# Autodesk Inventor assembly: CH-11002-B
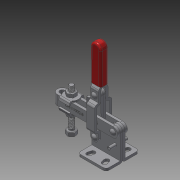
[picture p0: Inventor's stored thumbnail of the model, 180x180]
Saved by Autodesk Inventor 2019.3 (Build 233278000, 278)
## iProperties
Company: Î¢ÈíÖÐ¹ú
Created: 2012-09
Part Number: CH-11002-B
Material: Ogólny
Description: STEP AP203
Document SubType Name: Assembly
Designer: CADENGINEERING4
Stock Number: DOCISK PIONOWY
Sending System: SolidWorks 2010
Preprocessor: SwSTEP 2.0
Title: CH-11002-B.STEP
Author: Î¢ÈíÓÃ»§
Revision Number: ÈÎºÎ
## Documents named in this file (10)
- D:\Vault_2016\Projekty\Clamptek\STRONA\Vertical toggle clamp\CH-11002-B\CH-11002-B_ZAMKNIETY.iam
- D:\Vault_2016\Projekty\Clamptek\STRONA\Vertical toggle clamp\CH-11002-B\CH-FW-140.ipt
- D:\Vault_2016\Projekty\Clamptek\STRONA\Vertical toggle clamp\CH-11002-B\CH-11002-B-06.ipt
- D:\Vault_2016\Projekty\Clamptek\STRONA\Vertical toggle clamp\CH-11002-B\CH-11002-B-02 U-BAR.ipt
- D:\Vault_2016\Projekty\Clamptek\STRONA\Vertical toggle clamp\CH-11002-B\CH-11002-B-01 FLABGED BASE.ipt
- D:\Vault_2016\Projekty\Clamptek\STRONA\Vertical toggle clamp\CH-11002-B\M5 NUT.ipt
- D:\Vault_2016\Projekty\Clamptek\STRONA\Vertical toggle clamp\CH-11002-B\CH-11002-B-04 CONNECTING-PLATE.ipt
- D:\Vault_2016\Projekty\Clamptek\STRONA\Vertical toggle clamp\CH-11002-B\CH-11002-B-05.ipt
- D:\Vault_2016\Projekty\Clamptek\STRONA\Vertical toggle clamp\CH-11002-B\M5X40.ipt
- D:\Vault_2016\Projekty\Clamptek\STRONA\Vertical toggle clamp\CH-11002-B\CH-11002-B-03 HANDLE.ipt
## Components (14 placed, 14 different names)
1. CH-FW-140_1
2. CH-FW-140_2
3. CH-11002-B-06_3
4. CH-11002-B-02 U-BAR_4
5. CH-11002-B-06_5
6. CH-11002-B-01 FLABGED BASE_6
7. CH-11002-B-06_7
8. M5 NUT_8
9. M5 NUT_9
10. CH-11002-B-04 CONNECTING-PLATE_10
11. CH-11002-B-05_11
12. M5X40_12
13. CH-11002-B-06_13
14. CH-11002-B-03 HANDLE_14
